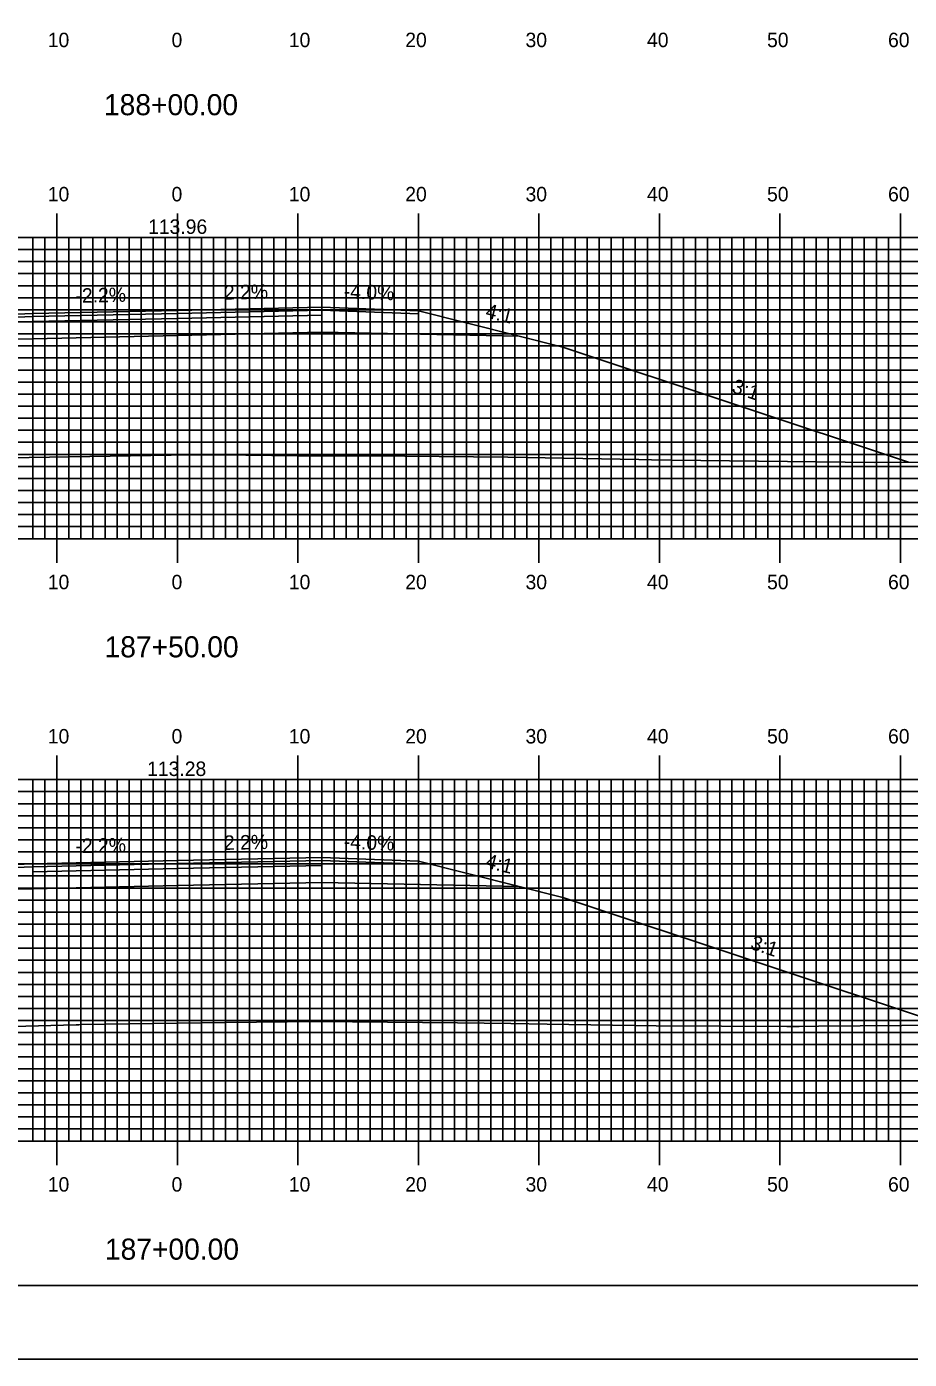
# Model space of a CAD drawing. Extents: x 1787763 to 1788106, y 442591 to 442811.
# Drawn here: x 1787916.1 to 1787989.4, y 442590.5 to 442701.2 of the extents above; entities that cross this region are included whole.
import ezdxf

# ---------------------------------------------------------------- set-up
doc = ezdxf.new("R2010")
doc.units = 0
for name, color, linetype in [('ANNOTATION', 7, 'Continuous'), ('BORDER', 7, 'Continuous'), ('D_Roadway_Centerline', 7, 'Continuous'), ('D_Roadway_Centerline_Text', 7, 'Continuous'), ('D_Roadway_Edge_Shoulder', 7, 'Continuous'), ('D_Roadway_Edge_TW', 7, 'Continuous'), ('D_Roadway_Pavement', 7, 'Continuous'), ('D_Roadway_SlopeLines', 7, 'Continuous'), ('D_Roadway_SubGrade', 7, 'Continuous'), ('H_V ANNOTATION', 7, 'Continuous'), ('MAJOR', 7, 'Continuous'), ('MINOR', 7, 'Continuous'), ('PLOT BOUNDARY', 7, 'Continuous'), ('S_Roadway_Centerline', 7, 'Continuous')]:
    doc.layers.add(name, color=color, linetype=linetype)

msp = doc.modelspace()

# ---------------------------------------------------------------- linework, layer by layer
at = {"layer": 'BORDER'}
msp.add_lwpolyline([(1787779.02, 442596.67), (1788099.02, 442596.67), (1788099.02, 442806.67), (1787779.02, 442806.67)], close=True, dxfattribs=at)
at = {"layer": 'D_Roadway_Centerline'}
for points in [[(1787868.67, 442664.72), (1787896.62, 442674.04), (1787900.25, 442674.95), (1787908.62, 442677.04), (1787916.62, 442677.36), (1787928.62, 442677.62), (1787940.62, 442677.89), (1787948.62, 442677.57), (1787956.98, 442675.48), (1787960.62, 442674.57), (1787989.3, 442665.01)], [(1787864.55, 442617.68), (1787896.62, 442628.37), (1787900.25, 442629.27), (1787908.62, 442631.37), (1787916.62, 442631.69), (1787928.62, 442631.95), (1787940.62, 442632.21), (1787948.62, 442631.89), (1787956.98, 442629.8), (1787960.62, 442628.89), (1787992.37, 442618.31)]]:
    msp.add_lwpolyline(points, dxfattribs=at)
at = {"layer": 'D_Roadway_Edge_Shoulder'}
for points in [[(1787916.62, 442677.36), (1787908.62, 442677.04), (1787908.62, 442676.79), (1787916.62, 442677.11)], [(1787940.62, 442677.89), (1787948.62, 442677.57), (1787948.62, 442677.32), (1787940.62, 442677.64)], [(1787916.62, 442631.69), (1787908.62, 442631.37), (1787908.62, 442631.12), (1787916.62, 442631.44)], [(1787940.62, 442632.21), (1787948.62, 442631.89), (1787948.62, 442631.64), (1787940.62, 442631.96)]]:
    msp.add_lwpolyline(points, close=True, dxfattribs=at)
at = {"layer": 'D_Roadway_Edge_TW'}
for points in [[(1787916.62, 442677.11), (1787916.62, 442677.36), (1787928.62, 442677.62), (1787940.62, 442677.89), (1787940.62, 442677.64), (1787928.62, 442677.37)], [(1787916.62, 442631.44), (1787916.62, 442631.69), (1787928.62, 442631.95), (1787940.62, 442632.21), (1787940.62, 442631.96), (1787928.62, 442631.7)]]:
    msp.add_lwpolyline(points, close=True, dxfattribs=at)
at = {"layer": 'D_Roadway_Pavement'}
for points in [[(1787916.62, 442676.69), (1787916.62, 442677.11), (1787928.62, 442677.37), (1787940.62, 442677.64), (1787940.62, 442677.22), (1787928.62, 442676.96)], [(1787916.62, 442631.02), (1787916.62, 442631.44), (1787928.62, 442631.7), (1787940.62, 442631.96), (1787940.62, 442631.55), (1787928.62, 442631.28)]]:
    msp.add_lwpolyline(points, close=True, dxfattribs=at)
at = {"layer": 'D_Roadway_SlopeLines'}
for points in [[(1787948.62, 442677.57), (1787960.62, 442674.57), (1787989.3, 442665.01)], [(1787948.62, 442631.89), (1787960.62, 442628.89), (1787992.37, 442618.31)]]:
    msp.add_lwpolyline(points, dxfattribs=at)
at = {"layer": 'D_Roadway_SubGrade'}
for points in [[(1787916.62, 442675.27), (1787900.25, 442674.95), (1787908.62, 442677.04), (1787908.62, 442676.79), (1787916.62, 442677.11), (1787928.62, 442677.37), (1787940.62, 442677.64), (1787948.62, 442677.32), (1787948.62, 442677.57), (1787956.98, 442675.48), (1787940.62, 442675.8), (1787928.62, 442675.54)], [(1787916.62, 442629.6), (1787900.25, 442629.27), (1787908.62, 442631.37), (1787908.62, 442631.12), (1787916.62, 442631.44), (1787928.62, 442631.7), (1787940.62, 442631.96), (1787948.62, 442631.64), (1787948.62, 442631.89), (1787956.98, 442629.8), (1787940.62, 442630.13), (1787928.62, 442629.87)]]:
    msp.add_lwpolyline(points, close=True, dxfattribs=at)
at = {"layer": 'MAJOR'}
for p, q in [((1787918.62, 442685.67), (1787918.62, 442683.67)), ((1787928.62, 442685.67), (1787928.62, 442683.67)), ((1787938.62, 442685.67), (1787938.62, 442683.67)), ((1787948.62, 442685.67), (1787948.62, 442683.67)), ((1787958.62, 442685.67), (1787958.62, 442683.67)), ((1787968.62, 442685.67), (1787968.62, 442683.67)), ((1787978.62, 442685.67), (1787978.62, 442683.67)), ((1787988.62, 442685.67), (1787988.62, 442683.67)), ((1787788.62, 442683.67), (1788068.62, 442683.67)), ((1787788.62, 442683.67), (1788068.62, 442683.67)), ((1787918.62, 442658.67), (1787918.62, 442683.67)), ((1787928.62, 442658.67), (1787928.62, 442683.67)), ((1787938.62, 442658.67), (1787938.62, 442683.67)), ((1787948.62, 442658.67), (1787948.62, 442683.67)), ((1787958.62, 442658.67), (1787958.62, 442683.67)), ((1787968.62, 442658.67), (1787968.62, 442683.67)), ((1787978.62, 442658.67), (1787978.62, 442683.67)), ((1787988.62, 442658.67), (1787988.62, 442683.67)), ((1787788.62, 442678.67), (1788068.62, 442678.67)), ((1787788.62, 442673.67), (1788068.62, 442673.67)), ((1787788.62, 442668.67), (1788068.62, 442668.67)), ((1787788.62, 442663.67), (1788068.62, 442663.67)), ((1787788.62, 442658.67), (1788068.62, 442658.67)), ((1787788.62, 442658.67), (1788068.62, 442658.67)), ((1787918.62, 442656.66), (1787918.62, 442658.67)), ((1787928.62, 442656.66), (1787928.62, 442658.67)), ((1787938.62, 442656.66), (1787938.62, 442658.67)), ((1787948.62, 442656.66), (1787948.62, 442658.67)), ((1787958.62, 442656.66), (1787958.62, 442658.67)), ((1787968.62, 442656.66), (1787968.62, 442658.67)), ((1787978.62, 442656.66), (1787978.62, 442658.67)), ((1787988.62, 442656.66), (1787988.62, 442658.67)), ((1787918.62, 442640.67), (1787918.62, 442638.67)), ((1787928.62, 442640.67), (1787928.62, 442638.67)), ((1787938.62, 442640.67), (1787938.62, 442638.67)), ((1787948.62, 442640.67), (1787948.62, 442638.67)), ((1787958.62, 442640.67), (1787958.62, 442638.67)), ((1787968.62, 442640.67), (1787968.62, 442638.67)), ((1787978.62, 442640.67), (1787978.62, 442638.67)), ((1787988.62, 442640.67), (1787988.62, 442638.67)), ((1787788.62, 442638.67), (1788068.62, 442638.67)), ((1787788.62, 442638.67), (1788068.62, 442638.67)), ((1787918.62, 442608.67), (1787918.62, 442638.67)), ((1787928.62, 442608.67), (1787928.62, 442638.67)), ((1787938.62, 442608.67), (1787938.62, 442638.67)), ((1787948.62, 442608.67), (1787948.62, 442638.67)), ((1787958.62, 442608.67), (1787958.62, 442638.67)), ((1787968.62, 442608.67), (1787968.62, 442638.67)), ((1787978.62, 442608.67), (1787978.62, 442638.67)), ((1787988.62, 442608.67), (1787988.62, 442638.67)), ((1787788.62, 442633.67), (1788068.62, 442633.67)), ((1787788.62, 442628.67), (1788068.62, 442628.67)), ((1787788.62, 442623.67), (1788068.62, 442623.67)), ((1787788.62, 442618.67), (1788068.62, 442618.67)), ((1787788.62, 442613.67), (1788068.62, 442613.67)), ((1787788.62, 442608.67), (1788068.62, 442608.67)), ((1787788.62, 442608.67), (1788068.62, 442608.67)), ((1787918.62, 442606.66), (1787918.62, 442608.67)), ((1787928.62, 442606.66), (1787928.62, 442608.67)), ((1787938.62, 442606.66), (1787938.62, 442608.67)), ((1787948.62, 442606.66), (1787948.62, 442608.67)), ((1787958.62, 442606.66), (1787958.62, 442608.67)), ((1787968.62, 442606.66), (1787968.62, 442608.67)), ((1787978.62, 442606.66), (1787978.62, 442608.67)), ((1787988.62, 442606.66), (1787988.62, 442608.67))]:
    msp.add_line(p, q, dxfattribs=at)
at = {"layer": 'MINOR'}
for p, q in [((1787916.62, 442658.67), (1787916.62, 442683.67)), ((1787917.62, 442658.67), (1787917.62, 442683.67)), ((1787919.62, 442658.67), (1787919.62, 442683.67)), ((1787920.62, 442658.67), (1787920.62, 442683.67)), ((1787921.62, 442658.67), (1787921.62, 442683.67)), ((1787922.62, 442658.67), (1787922.62, 442683.67)), ((1787923.62, 442658.67), (1787923.62, 442683.67)), ((1787924.62, 442658.67), (1787924.62, 442683.67)), ((1787925.62, 442658.67), (1787925.62, 442683.67)), ((1787926.62, 442658.67), (1787926.62, 442683.67)), ((1787927.62, 442658.67), (1787927.62, 442683.67)), ((1787929.62, 442658.67), (1787929.62, 442683.67)), ((1787930.62, 442658.67), (1787930.62, 442683.67)), ((1787931.62, 442658.67), (1787931.62, 442683.67)), ((1787932.62, 442658.67), (1787932.62, 442683.67)), ((1787933.62, 442658.67), (1787933.62, 442683.67)), ((1787934.62, 442658.67), (1787934.62, 442683.67)), ((1787935.62, 442658.67), (1787935.62, 442683.67)), ((1787936.62, 442658.67), (1787936.62, 442683.67)), ((1787937.62, 442658.67), (1787937.62, 442683.67)), ((1787939.62, 442658.67), (1787939.62, 442683.67)), ((1787940.62, 442658.67), (1787940.62, 442683.67)), ((1787941.62, 442658.67), (1787941.62, 442683.67)), ((1787942.62, 442658.67), (1787942.62, 442683.67)), ((1787943.62, 442658.67), (1787943.62, 442683.67)), ((1787944.62, 442658.67), (1787944.62, 442683.67)), ((1787945.62, 442658.67), (1787945.62, 442683.67)), ((1787946.62, 442658.67), (1787946.62, 442683.67)), ((1787947.62, 442658.67), (1787947.62, 442683.67)), ((1787949.62, 442658.67), (1787949.62, 442683.67)), ((1787950.62, 442658.67), (1787950.62, 442683.67)), ((1787951.62, 442658.67), (1787951.62, 442683.67)), ((1787952.62, 442658.67), (1787952.62, 442683.67)), ((1787953.62, 442658.67), (1787953.62, 442683.67)), ((1787954.62, 442658.67), (1787954.62, 442683.67)), ((1787955.62, 442658.67), (1787955.62, 442683.67)), ((1787956.62, 442658.67), (1787956.62, 442683.67)), ((1787957.62, 442658.67), (1787957.62, 442683.67)), ((1787959.62, 442658.67), (1787959.62, 442683.67)), ((1787960.62, 442658.67), (1787960.62, 442683.67)), ((1787961.62, 442658.67), (1787961.62, 442683.67)), ((1787962.62, 442658.67), (1787962.62, 442683.67)), ((1787963.62, 442658.67), (1787963.62, 442683.67)), ((1787964.62, 442658.67), (1787964.62, 442683.67)), ((1787965.62, 442658.67), (1787965.62, 442683.67)), ((1787966.62, 442658.67), (1787966.62, 442683.67)), ((1787967.62, 442658.67), (1787967.62, 442683.67)), ((1787969.62, 442658.67), (1787969.62, 442683.67)), ((1787970.62, 442658.67), (1787970.62, 442683.67)), ((1787971.62, 442658.67), (1787971.62, 442683.67)), ((1787972.62, 442658.67), (1787972.62, 442683.67)), ((1787973.62, 442658.67), (1787973.62, 442683.67)), ((1787974.62, 442658.67), (1787974.62, 442683.67)), ((1787975.62, 442658.67), (1787975.62, 442683.67)), ((1787976.62, 442658.67), (1787976.62, 442683.67)), ((1787977.62, 442658.67), (1787977.62, 442683.67)), ((1787979.62, 442658.67), (1787979.62, 442683.67)), ((1787980.62, 442658.67), (1787980.62, 442683.67)), ((1787981.62, 442658.67), (1787981.62, 442683.67)), ((1787982.62, 442658.67), (1787982.62, 442683.67)), ((1787983.62, 442658.67), (1787983.62, 442683.67)), ((1787984.62, 442658.67), (1787984.62, 442683.67)), ((1787985.62, 442658.67), (1787985.62, 442683.67)), ((1787986.62, 442658.67), (1787986.62, 442683.67)), ((1787987.62, 442658.67), (1787987.62, 442683.67)), ((1787788.62, 442682.67), (1788068.62, 442682.67)), ((1787788.62, 442681.67), (1788068.62, 442681.67)), ((1787788.62, 442680.67), (1788068.62, 442680.67)), ((1787788.62, 442679.67), (1788068.62, 442679.67)), ((1787788.62, 442677.67), (1788068.62, 442677.67)), ((1787788.62, 442676.67), (1788068.62, 442676.67)), ((1787788.62, 442675.67), (1788068.62, 442675.67)), ((1787788.62, 442674.67), (1788068.62, 442674.67)), ((1787788.62, 442672.67), (1788068.62, 442672.67)), ((1787788.62, 442671.67), (1788068.62, 442671.67)), ((1787788.62, 442670.67), (1788068.62, 442670.67)), ((1787788.62, 442669.67), (1788068.62, 442669.67)), ((1787788.62, 442667.67), (1788068.62, 442667.67)), ((1787788.62, 442666.67), (1788068.62, 442666.67)), ((1787788.62, 442665.67), (1788068.62, 442665.67)), ((1787788.62, 442664.67), (1788068.62, 442664.67)), ((1787788.62, 442662.67), (1788068.62, 442662.67)), ((1787788.62, 442661.67), (1788068.62, 442661.67)), ((1787788.62, 442660.67), (1788068.62, 442660.67)), ((1787788.62, 442659.67), (1788068.62, 442659.67)), ((1787916.62, 442608.67), (1787916.62, 442638.67)), ((1787917.62, 442608.67), (1787917.62, 442638.67)), ((1787919.62, 442608.67), (1787919.62, 442638.67)), ((1787920.62, 442608.67), (1787920.62, 442638.67)), ((1787921.62, 442608.67), (1787921.62, 442638.67)), ((1787922.62, 442608.67), (1787922.62, 442638.67)), ((1787923.62, 442608.67), (1787923.62, 442638.67)), ((1787924.62, 442608.67), (1787924.62, 442638.67)), ((1787925.62, 442608.67), (1787925.62, 442638.67)), ((1787926.62, 442608.67), (1787926.62, 442638.67)), ((1787927.62, 442608.67), (1787927.62, 442638.67)), ((1787929.62, 442608.67), (1787929.62, 442638.67)), ((1787930.62, 442608.67), (1787930.62, 442638.67)), ((1787931.62, 442608.67), (1787931.62, 442638.67)), ((1787932.62, 442608.67), (1787932.62, 442638.67)), ((1787933.62, 442608.67), (1787933.62, 442638.67)), ((1787934.62, 442608.67), (1787934.62, 442638.67)), ((1787935.62, 442608.67), (1787935.62, 442638.67)), ((1787936.62, 442608.67), (1787936.62, 442638.67)), ((1787937.62, 442608.67), (1787937.62, 442638.67)), ((1787939.62, 442608.67), (1787939.62, 442638.67)), ((1787940.62, 442608.67), (1787940.62, 442638.67)), ((1787941.62, 442608.67), (1787941.62, 442638.67)), ((1787942.62, 442608.67), (1787942.62, 442638.67)), ((1787943.62, 442608.67), (1787943.62, 442638.67)), ((1787944.62, 442608.67), (1787944.62, 442638.67)), ((1787945.62, 442608.67), (1787945.62, 442638.67)), ((1787946.62, 442608.67), (1787946.62, 442638.67)), ((1787947.62, 442608.67), (1787947.62, 442638.67)), ((1787949.62, 442608.67), (1787949.62, 442638.67)), ((1787950.62, 442608.67), (1787950.62, 442638.67)), ((1787951.62, 442608.67), (1787951.62, 442638.67)), ((1787952.62, 442608.67), (1787952.62, 442638.67)), ((1787953.62, 442608.67), (1787953.62, 442638.67)), ((1787954.62, 442608.67), (1787954.62, 442638.67)), ((1787955.62, 442608.67), (1787955.62, 442638.67)), ((1787956.62, 442608.67), (1787956.62, 442638.67)), ((1787957.62, 442608.67), (1787957.62, 442638.67)), ((1787959.62, 442608.67), (1787959.62, 442638.67)), ((1787960.62, 442608.67), (1787960.62, 442638.67)), ((1787961.62, 442608.67), (1787961.62, 442638.67)), ((1787962.62, 442608.67), (1787962.62, 442638.67)), ((1787963.62, 442608.67), (1787963.62, 442638.67)), ((1787964.62, 442608.67), (1787964.62, 442638.67)), ((1787965.62, 442608.67), (1787965.62, 442638.67)), ((1787966.62, 442608.67), (1787966.62, 442638.67)), ((1787967.62, 442608.67), (1787967.62, 442638.67)), ((1787969.62, 442608.67), (1787969.62, 442638.67)), ((1787970.62, 442608.67), (1787970.62, 442638.67)), ((1787971.62, 442608.67), (1787971.62, 442638.67)), ((1787972.62, 442608.67), (1787972.62, 442638.67)), ((1787973.62, 442608.67), (1787973.62, 442638.67)), ((1787974.62, 442608.67), (1787974.62, 442638.67)), ((1787975.62, 442608.67), (1787975.62, 442638.67)), ((1787976.62, 442608.67), (1787976.62, 442638.67)), ((1787977.62, 442608.67), (1787977.62, 442638.67)), ((1787979.62, 442608.67), (1787979.62, 442638.67)), ((1787980.62, 442608.67), (1787980.62, 442638.67)), ((1787981.62, 442608.67), (1787981.62, 442638.67)), ((1787982.62, 442608.67), (1787982.62, 442638.67)), ((1787983.62, 442608.67), (1787983.62, 442638.67)), ((1787984.62, 442608.67), (1787984.62, 442638.67)), ((1787985.62, 442608.67), (1787985.62, 442638.67)), ((1787986.62, 442608.67), (1787986.62, 442638.67)), ((1787987.62, 442608.67), (1787987.62, 442638.67)), ((1787788.62, 442637.67), (1788068.62, 442637.67)), ((1787788.62, 442636.67), (1788068.62, 442636.67)), ((1787788.62, 442635.67), (1788068.62, 442635.67)), ((1787788.62, 442634.67), (1788068.62, 442634.67)), ((1787788.62, 442632.67), (1788068.62, 442632.67)), ((1787788.62, 442631.67), (1788068.62, 442631.67)), ((1787788.62, 442630.67), (1788068.62, 442630.67)), ((1787788.62, 442629.67), (1788068.62, 442629.67)), ((1787788.62, 442627.67), (1788068.62, 442627.67)), ((1787788.62, 442626.67), (1788068.62, 442626.67)), ((1787788.62, 442625.67), (1788068.62, 442625.67)), ((1787788.62, 442624.67), (1788068.62, 442624.67)), ((1787788.62, 442622.67), (1788068.62, 442622.67)), ((1787788.62, 442621.67), (1788068.62, 442621.67)), ((1787788.62, 442620.67), (1788068.62, 442620.67)), ((1787788.62, 442619.67), (1788068.62, 442619.67)), ((1787788.62, 442617.67), (1788068.62, 442617.67)), ((1787788.62, 442616.67), (1788068.62, 442616.67)), ((1787788.62, 442615.67), (1788068.62, 442615.67)), ((1787788.62, 442614.67), (1788068.62, 442614.67)), ((1787788.62, 442612.67), (1788068.62, 442612.67)), ((1787788.62, 442611.67), (1788068.62, 442611.67)), ((1787788.62, 442610.67), (1788068.62, 442610.67)), ((1787788.62, 442609.67), (1788068.62, 442609.67))]:
    msp.add_line(p, q, dxfattribs=at)
at = {"layer": 'PLOT BOUNDARY'}
msp.add_lwpolyline([(1787762.83, 442590.55), (1788102.83, 442590.55), (1788102.83, 442810.55), (1787762.83, 442810.55)], close=True, dxfattribs=at)
at = {"layer": 'S_Roadway_Centerline'}
for points in [[(1787860.67, 442664.56), (1787869.64, 442664.74), (1787876.65, 442664.89), (1787888.8, 442664.98), (1787907.44, 442665.24), (1787908.3, 442665.27), (1787908.88, 442665.29), (1787911.24, 442665.32), (1787928.11, 442665.61), (1787932.16, 442665.63), (1787938.6, 442665.55), (1787947.5, 442665.51), (1787956.04, 442665.43), (1787966.92, 442665.24), (1787967.96, 442665.22), (1787969.65, 442665.19), (1787986.43, 442664.99), (1787991.8, 442665.02)], [(1787861.36, 442617.63), (1787862.19, 442617.62), (1787873.43, 442617.87), (1787881.58, 442617.84), (1787885, 442617.77), (1787890.61, 442617.73), (1787897.18, 442617.72), (1787901.39, 442617.82), (1787920.22, 442618.32), (1787920.45, 442618.32), (1787920.58, 442618.33), (1787932.67, 442618.51), (1787940.25, 442618.58), (1787951.87, 442618.49), (1787956.3, 442618.43), (1787959.3, 442618.37), (1787968.35, 442618.22), (1787979.19, 442618.18), (1787980.22, 442618.17), (1787981.81, 442618.19), (1787992.2, 442618.3)]]:
    msp.add_lwpolyline(points, dxfattribs=at)

# ---------------------------------------------------------------- texts
at = {"layer": 'ANNOTATION'}
for s, rotation, p in [('-2.2%', 1.2603, (1787920.18, 442678.24)), ('2.2%', 1.2603, (1787932.5, 442678.51)), ('-4.0%', 357.7094, (1787942.41, 442678.62)), ('4:1', 345.9638, (1787954.12, 442677.05)), ('3:1', 341.5652, (1787974.56, 442670.83)), ('-2.2%', 1.2603, (1787920.18, 442632.56)), ('2.2%', 1.2603, (1787932.5, 442632.83)), ('-4.0%', 357.7094, (1787942.41, 442632.94)), ('4:1', 345.9638, (1787954.12, 442631.38)), ('3:1', 341.5652, (1787976.1, 442624.64))]:
    msp.add_text(s, height=1.2, rotation=rotation, dxfattribs=at).set_placement(p)
at = {"layer": 'D_Roadway_Centerline'}
for s, p in [('C', (1787928.61, 442677.62)), ('L', (1787928.62, 442677.61)), ('C', (1787928.61, 442631.95)), ('L', (1787928.62, 442631.94))]:
    msp.add_text(s, height=0.0146, dxfattribs=at).set_placement(p)
at = {"layer": 'D_Roadway_Centerline_Text'}
for s, p in [('113.96', (1787926.19, 442683.97)), ('113.28', (1787926.11, 442638.97))]:
    msp.add_text(s, height=1.2, dxfattribs=at).set_placement(p)
at = {"layer": 'H_V ANNOTATION'}
for s, height, p in [('10', 1.2, (1787917.87, 442699.47)), ('0', 1.2, (1787928.14, 442699.47)), ('10', 1.2, (1787937.87, 442699.47)), ('20', 1.2, (1787947.53, 442699.47)), ('30', 1.2, (1787957.51, 442699.47)), ('40', 1.2, (1787967.59, 442699.47)), ('50', 1.2, (1787977.55, 442699.47)), ('60', 1.2, (1787987.59, 442699.47)), ('188+00.00', 1.75, (1787922.53, 442693.82)), ('10', 1.2, (1787917.87, 442686.67)), ('0', 1.2, (1787928.14, 442686.67)), ('10', 1.2, (1787937.87, 442686.67)), ('20', 1.2, (1787947.53, 442686.67)), ('30', 1.2, (1787957.51, 442686.67)), ('40', 1.2, (1787967.59, 442686.67)), ('50', 1.2, (1787977.55, 442686.67)), ('60', 1.2, (1787987.59, 442686.67)), ('10', 1.2, (1787917.87, 442654.47)), ('0', 1.2, (1787928.14, 442654.47)), ('10', 1.2, (1787937.87, 442654.47)), ('20', 1.2, (1787947.53, 442654.47)), ('30', 1.2, (1787957.51, 442654.47)), ('40', 1.2, (1787967.59, 442654.47)), ('50', 1.2, (1787977.55, 442654.47)), ('60', 1.2, (1787987.59, 442654.47)), ('187+50.00', 1.75, (1787922.58, 442648.82)), ('10', 1.2, (1787917.87, 442641.67)), ('0', 1.2, (1787928.14, 442641.67)), ('10', 1.2, (1787937.87, 442641.67)), ('20', 1.2, (1787947.53, 442641.67)), ('30', 1.2, (1787957.51, 442641.67)), ('40', 1.2, (1787967.59, 442641.67)), ('50', 1.2, (1787977.55, 442641.67)), ('60', 1.2, (1787987.59, 442641.67)), ('10', 1.2, (1787917.87, 442604.47)), ('0', 1.2, (1787928.14, 442604.47)), ('10', 1.2, (1787937.87, 442604.47)), ('20', 1.2, (1787947.53, 442604.47)), ('30', 1.2, (1787957.51, 442604.47)), ('40', 1.2, (1787967.59, 442604.47)), ('50', 1.2, (1787977.55, 442604.47)), ('60', 1.2, (1787987.59, 442604.47)), ('187+00.00', 1.75, (1787922.61, 442598.82))]:
    msp.add_text(s, height=height, dxfattribs=at).set_placement(p)

doc.saveas('drawing.dxf')
